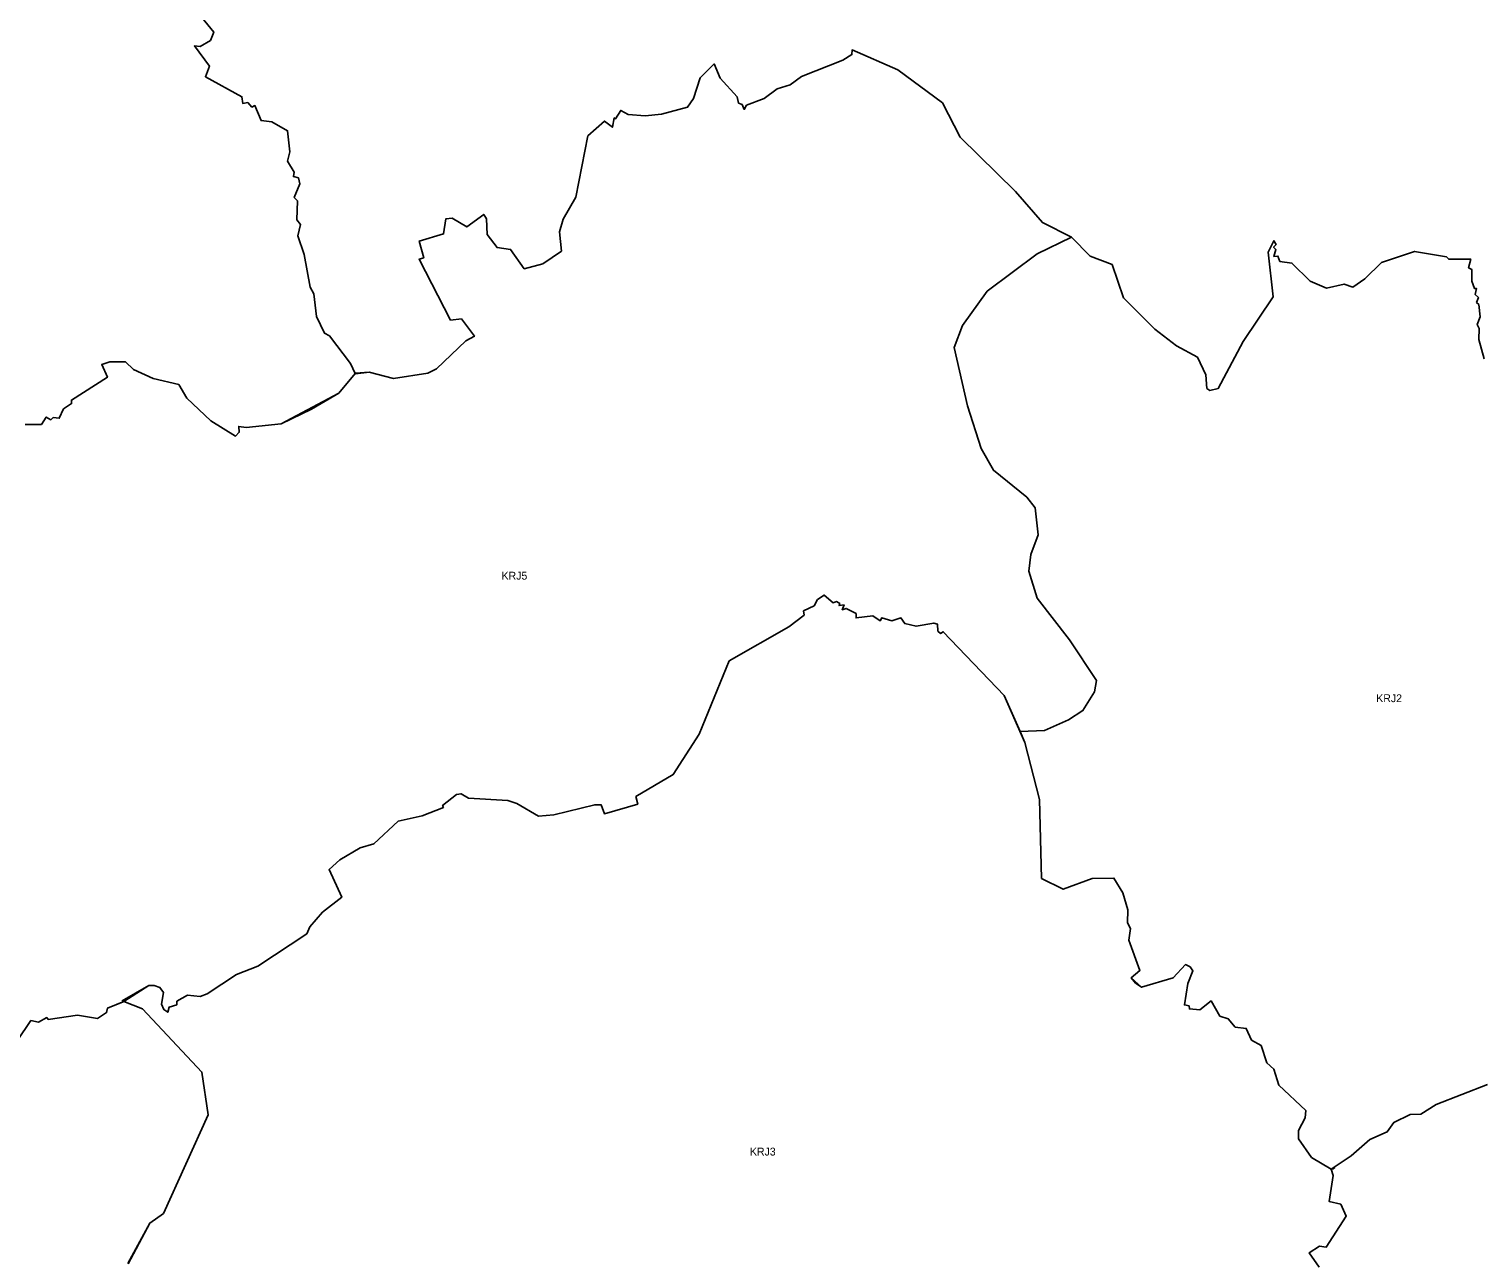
# Model space of a CAD drawing. Extents: x -563112 to -465432, y -1206259 to -1132144.
# Drawn here: x -510144 to -500917, y -1182409 to -1174583 of the extents above; entities that cross this region are included whole.
import ezdxf

# ---------------------------------------------------------------- set-up
doc = ezdxf.new("R2010")
doc.units = 0
doc.layers.add('krajiny', color=7, linetype='Continuous')

msp = doc.modelspace()

# ---------------------------------------------------------------- linework, layer by layer
at = {"layer": 'krajiny'}
for points in [[(-509043.58, -1174510.35), (-508968.44, -1174604.37), (-508989.61, -1174657.06), (-509055.14, -1174694.23), (-509090.85, -1174691.18), (-508995.87, -1174819.27), (-509021.1, -1174887.04), (-508788.55, -1175014.13), (-508784.11, -1175057.28), (-508752.11, -1175051.5), (-508725.48, -1175080.17), (-508706.37, -1175070.24), (-508667.36, -1175166.08), (-508598.62, -1175174.09), (-508498.62, -1175230.94), (-508483.37, -1175364.82), (-508499.52, -1175424.18), (-508457.59, -1175493.62), (-508461, -1175522.09), (-508429.3, -1175530.84), (-508420.47, -1175567.93), (-508456.26, -1175656.05), (-508435.67, -1175676.67), (-508439.99, -1175797.18), (-508415.26, -1175828.1), (-508433.91, -1175898.87), (-508393.49, -1176019.08), (-508354.03, -1176226.11), (-508330.57, -1176269.11), (-508314.62, -1176412.71), (-508263.71, -1176519.45), (-508232.59, -1176535.6), (-508097.52, -1176711.74), (-508067.76, -1176774.86), (-508172.58, -1176899.81), (-508540.1, -1177094.81), (-508762.2, -1177119.06), (-508809.62, -1177111.91), (-508805.74, -1177148.47), (-508830.86, -1177173.34), (-508986.61, -1177076.81), (-509138.86, -1176931.62), (-509190.71, -1176845.25), (-509353.11, -1176806.47), (-509479.89, -1176750.15), (-509530.54, -1176700.95), (-509630.15, -1176700.17), (-509680.88, -1176717.83), (-509644.38, -1176798.53), (-509873.9, -1176944.58), (-509872.98, -1176966.72), (-509923.42, -1177000.89), (-509951.38, -1177059.39), (-509989.85, -1177055.25), (-510004.43, -1177069.86), (-510033.84, -1177052.2), (-510065, -1177099.88), (-510169.22, -1177099.27)], [(-500884, -1176681), (-500919, -1176558), (-500917, -1176489), (-500930.22, -1176464.04), (-500909.09, -1176415.04), (-500918.04, -1176337.07), (-500932.91, -1176322.97), (-500920.94, -1176291.48), (-500941.58, -1176273.34), (-500933.7, -1176234.02), (-500946.56, -1176233.75), (-500962.75, -1176186.89), (-500963.73, -1176113.33), (-500983.44, -1176101.9), (-500970.02, -1176047.39), (-501110.16, -1176048.46), (-501124.65, -1176033.85), (-501326.87, -1175998.43), (-501538.42, -1176069.4), (-501643.91, -1176173.34), (-501720.54, -1176225.06), (-501775.52, -1176206.81), (-501888.11, -1176232.05), (-501991.71, -1176187.59), (-502107.97, -1176072.59), (-502184.22, -1176062.12), (-502197.34, -1176028.27), (-502222.89, -1176031.73), (-502209.86, -1175986.95), (-502224.77, -1175972.28), (-502208.8, -1175953.88), (-502222.22, -1175930.35), (-502259.42, -1176002.69), (-502226.33, -1176287.34), (-502418.24, -1176571.99), (-502577.06, -1176869.87), (-502630, -1176883.11), (-502649.85, -1176869.87), (-502656.47, -1176783.82), (-502709.41, -1176671.28), (-502841.76, -1176598.47), (-502980.73, -1176492.55), (-503179.25, -1176293.96), (-503252.05, -1176082.13), (-503391.01, -1176029.17), (-503510.13, -1175908.02), (-503695.42, -1175815.35), (-503867.47, -1175616.76), (-504218.2, -1175272.53), (-504330.7, -1175054.08), (-504615.25, -1174842.25), (-504906.55, -1174716.23), (-504907.15, -1174745.76), (-504966.23, -1174782.68), (-505229.37, -1174884.77), (-505300.81, -1174937.83), (-505383.93, -1174963.67), (-505465.38, -1175026.57), (-505577.61, -1175068.31), (-505593, -1175095), (-505606, -1175063), (-505629, -1175055), (-505638, -1175015), (-505745, -1174896), (-505785, -1174806), (-505873, -1174895), (-505916, -1175025), (-505953, -1175081), (-506120, -1175126), (-506224, -1175136), (-506331, -1175127), (-506379, -1175101), (-506411, -1175154), (-506420, -1175149), (-506432, -1175209), (-506482, -1175169), (-506588, -1175264), (-506665, -1175654), (-506745, -1175793), (-506769, -1175873), (-506755, -1175996), (-506873.33, -1176077.38), (-506992.35, -1176109.21), (-507079.57, -1175985.77), (-507165.47, -1175974.29), (-507227.71, -1175890.3), (-507232.26, -1175790.31), (-507250.08, -1175762.82), (-507357.34, -1175842.73), (-507451.68, -1175786.67), (-507491.22, -1175790.76), (-507505.9, -1175887.44), (-507660.24, -1175932.78), (-507631.8, -1176039.31), (-507661.55, -1176048.24), (-507461.17, -1176435.62), (-507392.33, -1176428.35), (-507309.14, -1176538.05), (-507363.28, -1176567.6), (-507550.07, -1176746.38), (-507605.54, -1176773.89), (-507824.99, -1176806.13), (-507979.32, -1176767.6), (-508067.05, -1176776.36), (-508067.76, -1176774.86), (-508097.52, -1176711.74), (-508232.59, -1176535.6), (-508263.71, -1176519.45), (-508314.62, -1176412.71), (-508330.57, -1176269.11), (-508354.03, -1176226.11), (-508393.49, -1176019.08), (-508433.91, -1175898.87), (-508415.26, -1175828.1), (-508439.99, -1175797.18), (-508435.67, -1175676.67), (-508456.26, -1175656.05), (-508420.47, -1175567.93), (-508429.3, -1175530.84), (-508461, -1175522.09), (-508457.59, -1175493.62), (-508499.52, -1175424.18), (-508483.37, -1175364.82), (-508498.62, -1175230.94), (-508598.62, -1175174.09), (-508667.36, -1175166.08), (-508706.37, -1175070.24), (-508725.48, -1175080.17), (-508752.11, -1175051.5), (-508784.11, -1175057.28), (-508788.55, -1175014.13), (-509021.1, -1174887.04), (-508995.87, -1174819.27), (-509090.85, -1174691.18), (-509055.14, -1174694.23), (-508989.61, -1174657.06), (-508968.44, -1174604.37), (-509043.58, -1174510.35)], [(-510169.22, -1177099.27), (-510065, -1177099.88), (-510033.84, -1177052.2), (-510004.43, -1177069.86), (-509989.85, -1177055.25), (-509951.38, -1177059.39), (-509923.42, -1177000.89), (-509872.98, -1176966.72), (-509873.9, -1176944.58), (-509644.38, -1176798.53), (-509680.88, -1176717.83), (-509630.15, -1176700.17), (-509530.54, -1176700.95), (-509479.89, -1176750.15), (-509353.11, -1176806.47), (-509190.71, -1176845.25), (-509138.86, -1176931.62), (-508986.61, -1177076.81), (-508830.86, -1177173.34), (-508805.74, -1177148.47), (-508809.62, -1177111.91), (-508762.2, -1177119.06), (-508540.1, -1177094.81), (-508345.89, -1177002.7), (-508172.58, -1176899.81), (-508067.76, -1176774.86), (-508067.05, -1176774.02), (-507979.32, -1176767.6), (-507824.99, -1176806.13), (-507605.54, -1176773.89), (-507550.07, -1176746.38), (-507363.28, -1176567.6), (-507309.14, -1176538.05), (-507392.33, -1176428.35), (-507461.17, -1176435.62), (-507661.55, -1176048.24), (-507631.8, -1176039.31), (-507660.24, -1175932.78), (-507505.9, -1175887.44), (-507491.22, -1175790.76), (-507451.68, -1175786.67), (-507357.34, -1175842.73), (-507250.08, -1175762.82), (-507232.26, -1175790.31), (-507227.71, -1175890.3), (-507165.47, -1175974.29), (-507079.57, -1175985.77), (-506992.35, -1176109.21), (-506873.33, -1176077.38), (-506755, -1175996), (-506769, -1175873), (-506745, -1175793), (-506665, -1175654), (-506588, -1175264), (-506482, -1175169), (-506432, -1175209), (-506420, -1175149), (-506411, -1175154), (-506379, -1175101), (-506331, -1175127), (-506224, -1175136), (-506120, -1175126), (-505953, -1175081), (-505916, -1175025), (-505873, -1174895), (-505785, -1174806), (-505745, -1174896), (-505638, -1175015), (-505629, -1175055), (-505606, -1175063), (-505593, -1175095), (-505577.61, -1175068.31), (-505465.38, -1175026.57), (-505383.93, -1174963.67), (-505300.81, -1174937.83), (-505229.37, -1174884.77), (-504966.23, -1174782.68), (-504907.15, -1174745.76), (-504906.55, -1174716.23), (-504615.25, -1174842.25), (-504330.7, -1175054.08), (-504218.2, -1175272.53), (-503867.47, -1175616.76), (-503695.42, -1175815.35), (-503510.13, -1175908.02), (-503728.51, -1176013.94), (-504046.15, -1176252.25), (-504204.97, -1176470.7), (-504257.91, -1176609.71), (-504171.88, -1176980.42), (-504085.85, -1177251.82), (-504006.44, -1177390.84), (-503794.68, -1177562.95), (-503741.74, -1177629.15), (-503721.89, -1177801.26), (-503768.21, -1177927.03), (-503781.45, -1178032.95), (-503728.51, -1178205.06), (-503523.36, -1178469.85), (-503351.31, -1178728.02), (-503364.54, -1178800.83), (-503437.34, -1178919.99), (-503529.98, -1178979.56), (-503682.18, -1179045.76), (-503837.77, -1179053.17), (-503939.61, -1178823.97), (-504326.08, -1178418.36), (-504343.27, -1178429.15), (-504361.24, -1178413.67), (-504362.69, -1178370.94), (-504387.26, -1178363.08), (-504498.95, -1178383.09), (-504571.06, -1178365.97), (-504595.4, -1178330.72), (-504654.24, -1178348.12), (-504717.45, -1178329.06), (-504727.06, -1178347.97), (-504774.06, -1178317.7), (-504880.59, -1178329.94), (-504881.12, -1178302.26), (-504943.57, -1178270.08), (-504968.82, -1178278.41), (-504957.45, -1178247.54), (-504988.94, -1178251.85), (-504984.63, -1178239.15), (-505005.8, -1178226.53), (-505027.15, -1178233.81), (-505083.22, -1178184.58), (-505126.89, -1178213.95), (-505148.31, -1178253.81), (-505215.11, -1178285.82), (-505210.78, -1178312.64), (-505308.25, -1178386.57), (-505687.91, -1178603.92), (-505878.54, -1179068.89), (-506043.98, -1179327.06), (-506282.21, -1179466.08), (-506270.04, -1179514.68), (-506482.76, -1179575.75), (-506502.64, -1179519.55), (-506543.86, -1179518.61), (-506803.39, -1179582.73), (-506901.81, -1179591.85), (-507039.22, -1179510.24), (-507096.58, -1179492.43), (-507347.24, -1179477.63), (-507394.32, -1179448.65), (-507423.38, -1179453.53), (-507512.49, -1179523.52), (-507506.5, -1179535.78), (-507641.84, -1179588.68), (-507794.14, -1179622.81), (-507950.08, -1179766.68), (-508036.14, -1179794.03), (-508165.47, -1179869.72), (-508234.45, -1179930.36), (-508152.46, -1180106.83), (-508275.5, -1180202.18), (-508356.38, -1180295.15), (-508376.02, -1180339.49), (-508687.66, -1180546.19), (-508823.99, -1180597.86), (-509011.01, -1180720.94), (-509054.57, -1180738.26), (-509134.71, -1180729.45), (-509202.6, -1180768.79), (-509203.96, -1180791.59), (-509252.71, -1180806.92), (-509260.74, -1180838.93), (-509286.91, -1180822.57), (-509300.32, -1180788.66), (-509288.52, -1180712.59), (-509310.38, -1180682.29), (-509347.57, -1180669.32), (-509381.33, -1180669.6), (-509540.03, -1180769.6), (-509548.28, -1180774.8), (-509644.44, -1180813.56), (-509650.3, -1180841.52), (-509707.54, -1180878.81), (-509834.91, -1180857.83), (-510020.89, -1180885.17), (-510031.18, -1180872.51), (-510083.79, -1180901.42), (-510131.17, -1180891.9), (-510219.2, -1181021.29)], [(-500863.78, -1181298.14), (-501190.97, -1181426.32), (-501288.53, -1181487.62), (-501355.52, -1181490.47), (-501459.85, -1181540.5), (-501500.99, -1181599.23), (-501612.04, -1181649.43), (-501731.01, -1181752.47), (-501859, -1181837), (-501983, -1181763), (-502066, -1181644), (-502067, -1181592), (-502023, -1181510), (-502019, -1181465), (-502191, -1181303), (-502224, -1181201), (-502268, -1181160), (-502304, -1181051), (-502366, -1181016), (-502398, -1180942), (-502468, -1180934), (-502513, -1180881), (-502566, -1180863), (-502622, -1180767), (-502693, -1180824), (-502760, -1180818), (-502762, -1180799), (-502792, -1180792), (-502770, -1180656), (-502738, -1180576), (-502755, -1180551), (-502785, -1180536), (-502864, -1180620), (-503064, -1180680), (-503130, -1180620), (-503075, -1180574), (-503145, -1180381), (-503136, -1180307), (-503155, -1180271), (-503151, -1180187), (-503183, -1180080), (-503241, -1179985), (-503379, -1179989), (-503563, -1180057), (-503701.93, -1179987.05), (-503714.61, -1179485.94), (-503807.26, -1179121.85), (-503837.77, -1179053.17), (-503682.18, -1179045.76), (-503529.98, -1178979.56), (-503437.34, -1178919.99), (-503364.54, -1178800.83), (-503351.31, -1178728.02), (-503523.36, -1178469.85), (-503728.51, -1178205.06), (-503781.45, -1178032.95), (-503768.21, -1177927.03), (-503721.89, -1177801.26), (-503741.74, -1177629.15), (-503794.68, -1177562.95), (-504006.44, -1177390.84), (-504085.85, -1177251.82), (-504171.88, -1176980.42), (-504257.91, -1176609.71), (-504204.97, -1176470.7), (-504046.15, -1176252.25), (-503728.51, -1176013.94), (-503510.13, -1175908.02), (-503391.01, -1176029.17), (-503252.05, -1176082.13), (-503179.25, -1176293.96), (-502980.73, -1176492.55), (-502841.76, -1176598.47), (-502709.41, -1176671.28), (-502656.47, -1176783.82), (-502649.85, -1176869.87), (-502630, -1176883.11), (-502577.06, -1176869.87), (-502418.24, -1176571.99), (-502226.33, -1176287.34), (-502259.42, -1176002.69), (-502222.22, -1175930.35), (-502208.8, -1175953.88), (-502224.77, -1175972.28), (-502209.86, -1175986.95), (-502222.89, -1176031.73), (-502197.34, -1176028.27), (-502184.22, -1176062.12), (-502107.97, -1176072.59), (-501991.71, -1176187.59), (-501888.11, -1176232.05), (-501775.52, -1176206.81), (-501720.54, -1176225.06), (-501643.91, -1176173.34), (-501538.42, -1176069.4), (-501326.87, -1175998.43), (-501124.65, -1176033.85), (-501110.16, -1176048.46), (-500970.02, -1176047.39), (-500983.44, -1176101.9), (-500963.73, -1176113.33), (-500962.75, -1176186.89), (-500946.56, -1176233.75), (-500933.7, -1176234.02), (-500941.58, -1176273.34), (-500920.94, -1176291.48), (-500932.91, -1176322.97), (-500918.04, -1176337.07), (-500909.09, -1176415.04), (-500930.22, -1176464.04), (-500917, -1176489), (-500919, -1176558), (-500884, -1176681)], [(-509513.77, -1182440.13), (-509374.46, -1182179.88), (-509288.44, -1182120.31), (-509003.92, -1181491.51), (-509043.62, -1181220.13), (-509420.78, -1180816.37), (-509540.03, -1180769.6), (-509550.83, -1180765.37), (-509381.33, -1180669.6), (-509347.57, -1180669.32), (-509310.38, -1180682.29), (-509288.52, -1180712.59), (-509300.32, -1180788.66), (-509286.91, -1180822.57), (-509260.74, -1180838.93), (-509252.71, -1180806.92), (-509203.96, -1180791.59), (-509202.6, -1180768.79), (-509134.71, -1180729.45), (-509054.57, -1180738.26), (-509011.01, -1180720.94), (-508823.99, -1180597.86), (-508687.66, -1180546.19), (-508376.02, -1180339.49), (-508356.38, -1180295.15), (-508275.5, -1180202.18), (-508152.46, -1180106.83), (-508234.45, -1179930.36), (-508165.47, -1179869.72), (-508036.14, -1179794.03), (-507950.08, -1179766.68), (-507794.14, -1179622.81), (-507641.84, -1179588.68), (-507506.5, -1179535.78), (-507512.49, -1179523.52), (-507423.38, -1179453.53), (-507394.32, -1179448.65), (-507347.24, -1179477.63), (-507096.58, -1179492.43), (-507039.22, -1179510.24), (-506901.81, -1179591.85), (-506803.39, -1179582.73), (-506543.86, -1179518.61), (-506502.64, -1179519.55), (-506482.76, -1179575.75), (-506270.04, -1179514.68), (-506282.21, -1179466.08), (-506043.98, -1179327.06), (-505878.54, -1179068.89), (-505687.91, -1178603.92), (-505308.25, -1178386.57), (-505210.78, -1178312.64), (-505215.11, -1178285.82), (-505148.31, -1178253.81), (-505126.89, -1178213.95), (-505083.22, -1178184.58), (-505027.15, -1178233.81), (-505005.8, -1178226.53), (-504984.63, -1178239.15), (-504988.94, -1178251.85), (-504957.45, -1178247.54), (-504968.82, -1178278.41), (-504943.57, -1178270.08), (-504881.12, -1178302.26), (-504880.59, -1178329.94), (-504774.06, -1178317.7), (-504727.06, -1178347.97), (-504717.45, -1178329.06), (-504654.24, -1178348.12), (-504595.4, -1178330.72), (-504571.06, -1178365.97), (-504498.95, -1178383.09), (-504387.26, -1178363.08), (-504362.69, -1178370.94), (-504361.24, -1178413.67), (-504343.27, -1178429.15), (-504326.08, -1178418.36), (-503939.61, -1178823.97), (-503807.26, -1179121.85), (-503714.61, -1179485.94), (-503701.93, -1179987.05), (-503563, -1180057), (-503379, -1179989), (-503241, -1179985), (-503183, -1180080), (-503151, -1180187), (-503155, -1180271), (-503136, -1180307), (-503145, -1180381), (-503075, -1180574), (-503130, -1180620), (-503104, -1180653), (-503064, -1180680), (-502864, -1180620), (-502785, -1180536), (-502755, -1180551), (-502738, -1180576), (-502770, -1180656), (-502792, -1180792), (-502762, -1180799), (-502760, -1180818), (-502693, -1180824), (-502622, -1180767), (-502566, -1180863), (-502513, -1180881), (-502468, -1180934), (-502398, -1180942), (-502366, -1181016), (-502304, -1181051), (-502268, -1181160), (-502224, -1181201), (-502191, -1181303), (-502019, -1181465), (-502023, -1181510), (-502067, -1181592), (-502066, -1181644), (-501983, -1181763), (-501859, -1181837), (-501845, -1181877), (-501871, -1182043), (-501797, -1182060), (-501762, -1182136), (-501889, -1182333), (-501933, -1182327), (-501998, -1182369), (-501934, -1182460)], [(-510219.2, -1181021.29), (-510131.17, -1180891.9), (-510083.79, -1180901.42), (-510031.18, -1180872.51), (-510020.89, -1180885.17), (-509834.91, -1180857.83), (-509707.54, -1180878.81), (-509650.3, -1180841.52), (-509644.44, -1180813.56), (-509540.03, -1180769.6), (-509420.78, -1180816.37), (-509043.62, -1181220.13), (-509003.92, -1181491.51), (-509288.44, -1182120.31), (-509374.46, -1182179.88), (-509515.64, -1182438.33)], [(-501934, -1182460), (-501998, -1182369), (-501933, -1182327), (-501889, -1182333), (-501762, -1182136), (-501797, -1182060), (-501871, -1182043), (-501845, -1181877), (-501859, -1181837), (-501731.01, -1181752.47), (-501612.04, -1181649.43), (-501500.99, -1181599.23), (-501459.85, -1181540.5), (-501355.52, -1181490.47), (-501288.53, -1181487.62), (-501190.97, -1181426.32), (-500863.78, -1181298.14)]]:
    msp.add_lwpolyline(points, dxfattribs=at)
msp.add_lwpolyline([(-501859, -1181837), (-501835.24, -1181825.95), (-501846.08, -1181834.94)], close=True, dxfattribs=at)

# ---------------------------------------------------------------- texts
for s, p in [('KRJ5', (-507136.59, -1178086.69)), ('KRJ2', (-501570.96, -1178866.16)), ('KRJ3', (-505556.41, -1181750.55))]:
    msp.add_text(s, height=50, dxfattribs=at).set_placement(p)

doc.saveas('drawing.dxf')
